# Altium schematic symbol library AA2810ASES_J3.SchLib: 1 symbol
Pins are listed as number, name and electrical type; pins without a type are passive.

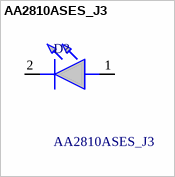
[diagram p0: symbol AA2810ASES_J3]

## AA2810ASES_J3
designator D?
Standard LEDs - SMD RA Red 625nm 1800mcd 110deg Water Clr; Manufacturer_Name: Kingbright; Manufacturer_Part_Number: AA2810ASES/J3; Geometry.Height: 0.9mm
footprint AA2810ASESJ3
pins: 1 A, 2 K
